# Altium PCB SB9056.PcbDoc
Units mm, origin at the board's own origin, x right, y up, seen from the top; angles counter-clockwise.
Board outline 90 x 56 mm, 2 copper layers (Top Layer, Bottom Layer); 0 components, 0 nets, 4 pads, 0 vias.
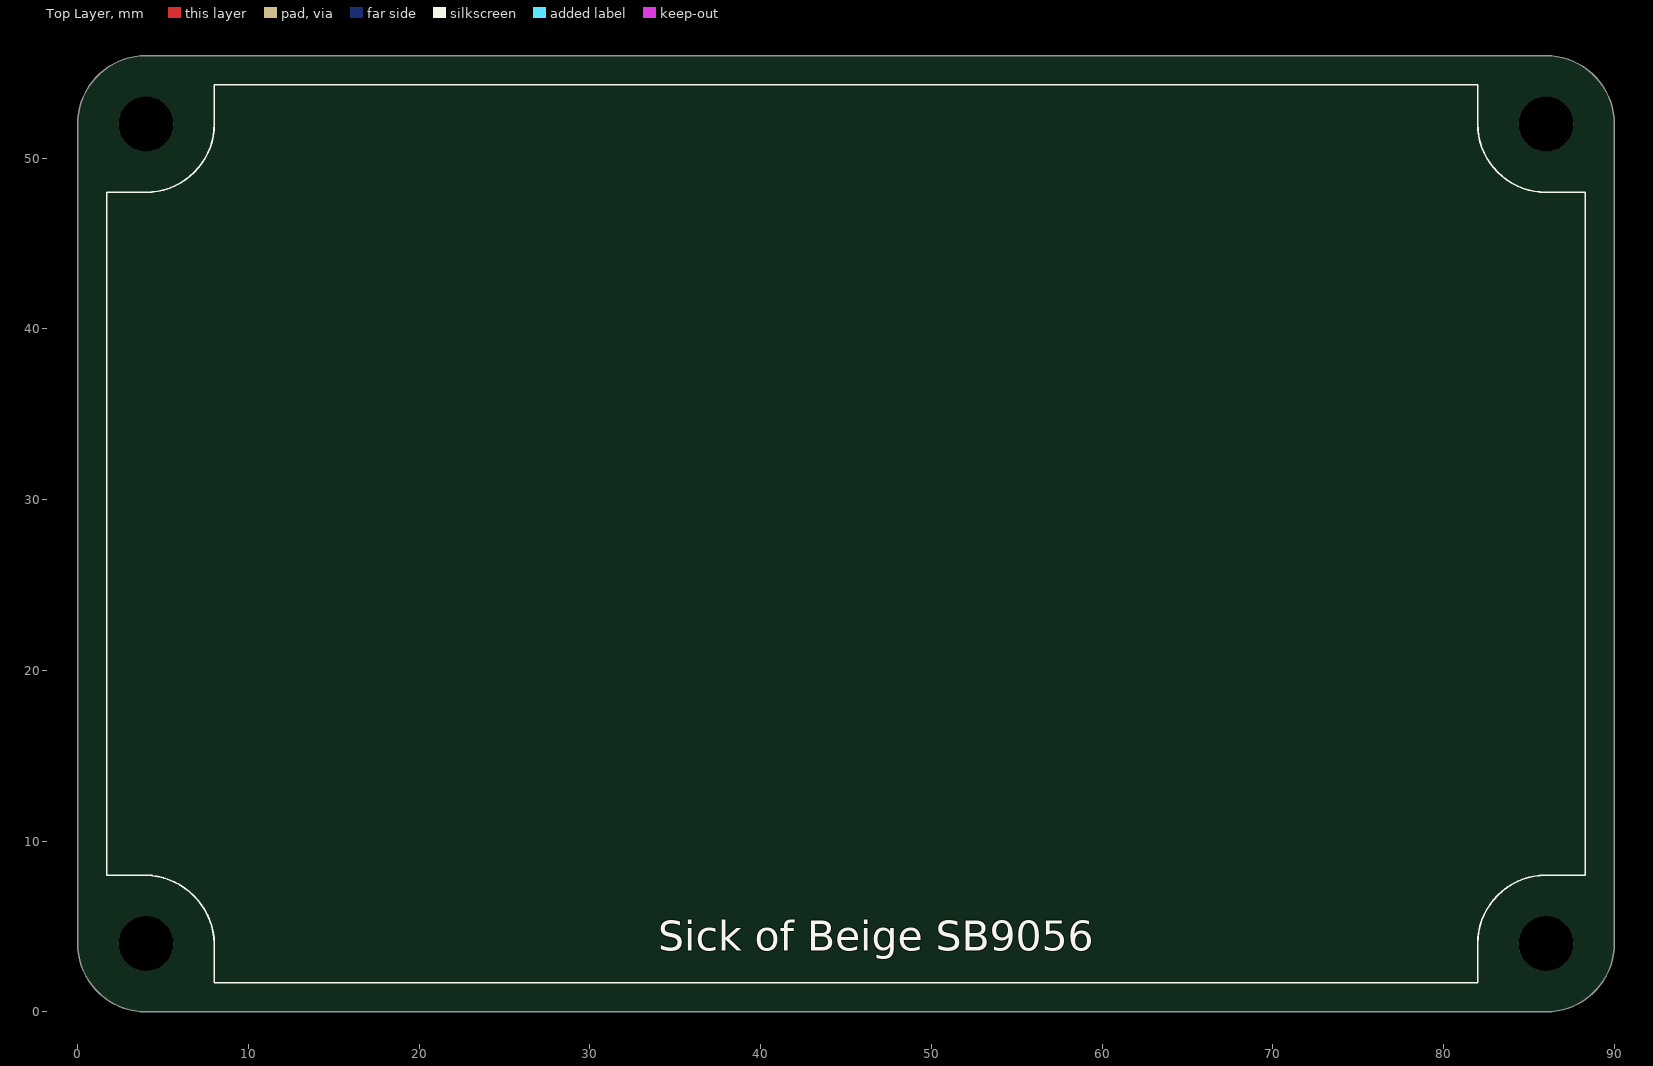
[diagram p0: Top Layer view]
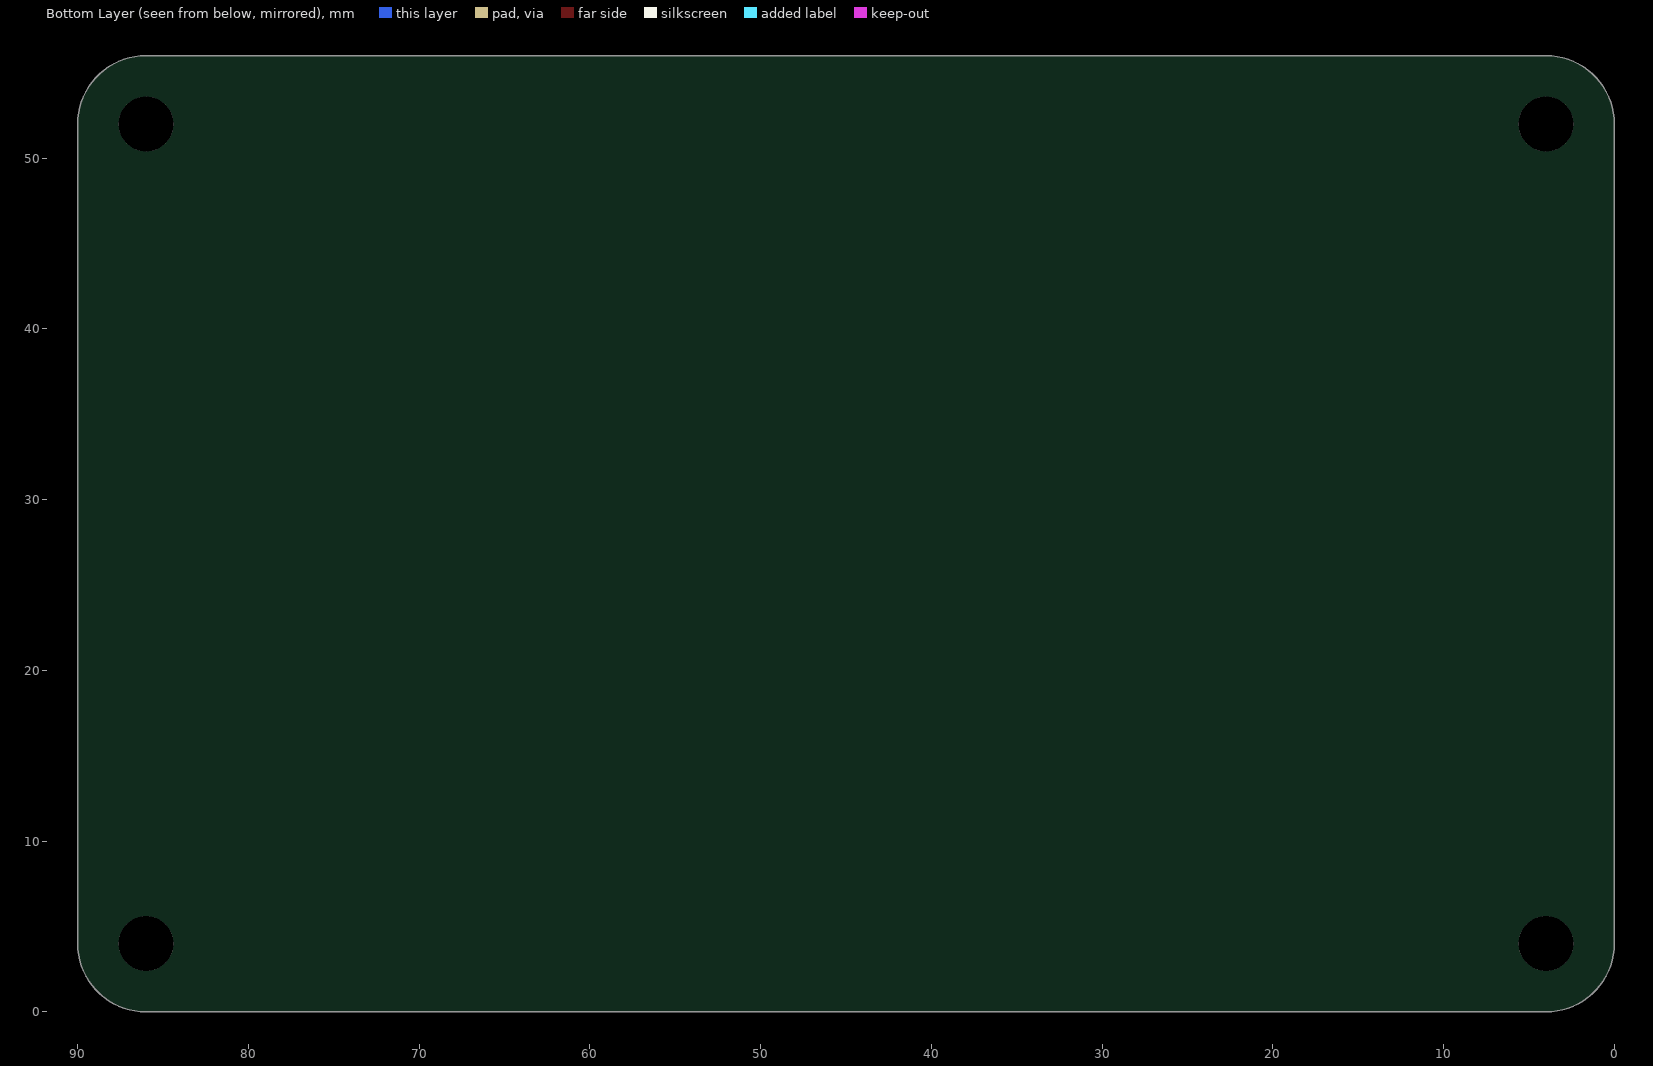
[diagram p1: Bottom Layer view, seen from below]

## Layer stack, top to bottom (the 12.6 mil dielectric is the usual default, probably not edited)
Top Layer: signal copper 0.0356
Dielectric: dielectric 0.32, FR-4, Dk 4.8
Bottom Layer: signal copper 0.0356

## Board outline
0,4 0,52 cw(c4,52) 4,56 86,56 cw(c86,52) 90,52 90,4 cw(c86,4) 86,0 4,0 cw(c4,4)

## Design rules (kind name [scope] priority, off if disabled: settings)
Clearance [All] p1: gap=0.254
PolygonConnect [All] p1: connectstyle=Relief reliefconductorwidth=0.254 reliefentries=4 polygonreliefangle="90 Angle" airgapwidth=0.254
RoutingVias [All] p1: holewidth=0.711 width=1.27 viastyle="Through Hole" minholewidth=0.711 minwidth=1.27 maxholewidth=0.711 maxwidth=1.27
SolderMaskExpansion [All] p1: expansion=0.102
Width [All] p1: maxlimit=0.254 minlimit=0.254 preferedwidth=0.254
28 further rules are at their usual default settings.

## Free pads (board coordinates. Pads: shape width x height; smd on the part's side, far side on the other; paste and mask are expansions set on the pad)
  round 3.2 hole 3.2 unplated: 0(4,4) 1(4,52) 2(86,52) 3(86,4)

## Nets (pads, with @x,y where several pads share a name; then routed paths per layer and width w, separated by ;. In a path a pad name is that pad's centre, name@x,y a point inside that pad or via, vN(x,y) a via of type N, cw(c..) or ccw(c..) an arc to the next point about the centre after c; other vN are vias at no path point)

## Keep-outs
Top Overlay:
  lines w0.102: 1.7,8 4,8 cw(c3.9,3.9) 8,4 8,1.7 82,1.7 82,4 cw(c86,4) 86,8 88.3,8 88.3,48 86,48 cw(c86,52) 82,52 82,54.3 8,54.3 8,52 cw(c4,52) 4,48 1.7,48 1.7,8

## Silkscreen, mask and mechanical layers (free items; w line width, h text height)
Top Overlay:
  text "Sick of Beige SB9056" at 34,3 h3
Mechanical 1:
  the board outline again, w0.102
Mechanical 4:
  circle w0.102: c86,4 r1.6
  circle w0.102: c4,4 r1.6
  circle w0.102: c4,52 r1.6
  circle w0.102: c86,52 r1.6
  lines w0.102: 0,28 90,28 ; 45,0 45,56

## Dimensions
86,56 to 86,0 on Mechanical 3
0,4 to 90,4 on Mechanical 3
